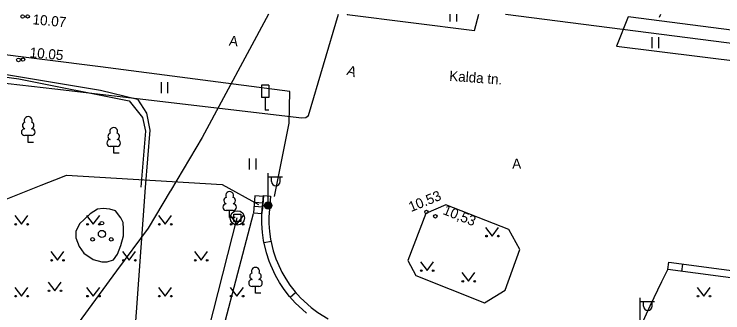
# Model space of a CAD drawing. Extents: x 713497 to 713863, y 6590062 to 6590327.
# Drawn here: x 713659.5 to 713708.83, y 6590306.61 to 6590327.39 of the extents above; entities that cross this region are included whole.
import ezdxf

# ---------------------------------------------------------------- set-up
doc = ezdxf.new("R2010")
doc.units = 0
for name, color, linetype in [('AED', 7, 'Continuous'), ('DKAEV', 7, 'Continuous'), ('HALJASTUS', 7, 'Continuous'), ('HOONE', 7, 'Continuous'), ('KORGUS', 7, 'Continuous'), ('KPKAABEL', 7, 'Continuous'), ('LIIKLUS', 7, 'Continuous'), ('MPKAABEL', 7, 'Continuous'), ('POST', 7, 'Continuous'), ('PUU', 7, 'Continuous'), ('SITRASS', 7, 'Continuous'), ('TEE', 7, 'Continuous'), ('VTRASS', 7, 'Continuous')]:
    doc.layers.add(name, color=color, linetype=linetype)

msp = doc.modelspace()

# ---------------------------------------------------------------- linework, layer by layer
at = {"layer": 'AED'}
for points in [[(713679.847, 6590306.599), (713679.073, 6590307.305), (713678.668, 6590307.755), (713678.294, 6590308.239), (713677.979, 6590308.711), (713677.695, 6590309.209), (713677.362, 6590309.92), (713677.251, 6590310.204), (713677.059, 6590310.788), (713676.86, 6590311.653), (713676.782, 6590312.21), (713676.74, 6590312.819), (713676.737, 6590313.526), (713676.863, 6590314.765), (713676.791, 6590313.828), (713676.863, 6590314.765), (713677.341, 6590314.719), (713677.238, 6590313.258), (713677.24, 6590312.837), (713677.28, 6590312.261), (713677.352, 6590311.744), (713677.541, 6590310.923), (713677.722, 6590310.373), (713677.822, 6590310.117), (713678.139, 6590309.439), (713678.405, 6590308.974), (713678.7, 6590308.532), (713679.053, 6590308.076), (713679.429, 6590307.657), (713680.165, 6590306.986), (713680.628, 6590306.643), (713681.358, 6590306.198)], [(713705.062, 6590310.126), (713726.713, 6590307.265), (713727.852, 6590308.18), (713734.626, 6590314.242), (713739.654, 6590313.67), (713739.599, 6590313.184), (713734.778, 6590313.732), (713728.099, 6590307.754), (713726.875, 6590306.739), (713704.996, 6590309.63)], [(713676.897, 6590311.494), (713677.384, 6590311.607)], [(713704.996, 6590309.63), (713705.062, 6590310.126)], [(713705.988, 6590309.499), (713706.053, 6590309.995)], [(713678.716, 6590307.703), (713679.088, 6590308.037)]]:
    msp.add_lwpolyline(points, dxfattribs=at)
at = {"layer": 'DKAEV'}
for p, q in [((713674.785, 6590312.967), (713674.785, 6590313.467)), ((713674.785, 6590313.467), (713675.285, 6590313.467)), ((713675.285, 6590313.467), (713675.285, 6590312.967)), ((713675.285, 6590312.967), (713674.785, 6590312.967))]:
    msp.add_line(p, q, dxfattribs=at)
msp.add_circle((713675.035, 6590313.217), 0.5, dxfattribs=at)
at = {"layer": 'HALJASTUS'}
for p, q in [((713689.826, 6590327.391), (713689.826, 6590326.888)), ((713690.281, 6590327.391), (713690.281, 6590326.888)), ((713703.899, 6590325.785), (713703.899, 6590325.024)), ((713704.354, 6590325.785), (713704.354, 6590325.024)), ((713669.727, 6590322.66), (713669.727, 6590321.899)), ((713670.182, 6590322.66), (713670.182, 6590321.899)), ((713675.864, 6590317.355), (713675.864, 6590316.594)), ((713676.319, 6590317.355), (713676.319, 6590316.594)), ((713659.547, 6590313.377), (713660.01, 6590312.77)), ((713660.01, 6590312.77), (713660.456, 6590313.377)), ((713664.547, 6590313.377), (713665.01, 6590312.77)), ((713665.01, 6590312.77), (713665.456, 6590313.377)), ((713669.547, 6590313.377), (713670.01, 6590312.77)), ((713670.01, 6590312.77), (713670.456, 6590313.377)), ((713674.547, 6590313.377), (713675.01, 6590312.77)), ((713675.01, 6590312.77), (713675.456, 6590313.377)), ((713692.317, 6590312.557), (713692.78, 6590311.95)), ((713692.78, 6590311.95), (713693.226, 6590312.557)), ((713662.047, 6590310.877), (713662.51, 6590310.27)), ((713662.51, 6590310.27), (713662.956, 6590310.877)), ((713667.047, 6590310.877), (713667.51, 6590310.27)), ((713667.51, 6590310.27), (713667.956, 6590310.877)), ((713672.047, 6590310.877), (713672.51, 6590310.27)), ((713672.51, 6590310.27), (713672.956, 6590310.877)), ((713687.777, 6590310.157), (713688.24, 6590309.55)), ((713688.24, 6590309.55), (713688.686, 6590310.157)), ((713690.667, 6590309.417), (713691.13, 6590308.81)), ((713691.13, 6590308.81), (713691.576, 6590309.417)), ((713661.867, 6590308.747), (713662.33, 6590308.14)), ((713662.33, 6590308.14), (713662.776, 6590308.747)), ((713659.547, 6590308.377), (713660.01, 6590307.77)), ((713660.01, 6590307.77), (713660.456, 6590308.377)), ((713664.547, 6590308.377), (713665.01, 6590307.77)), ((713665.01, 6590307.77), (713665.456, 6590308.377)), ((713669.547, 6590308.377), (713670.01, 6590307.77)), ((713670.01, 6590307.77), (713670.456, 6590308.377)), ((713674.547, 6590308.377), (713675.01, 6590307.77)), ((713675.01, 6590307.77), (713675.456, 6590308.377)), ((713707.047, 6590308.377), (713707.51, 6590307.77)), ((713707.51, 6590307.77), (713707.956, 6590308.377))]:
    msp.add_line(p, q, dxfattribs=at)
msp.add_lwpolyline([(713664.34, 6590310.76), (713665.01, 6590310.33), (713665.61, 6590310.15), (713665.98, 6590310.15), (713666.42, 6590310.3), (713666.7, 6590310.69), (713666.93, 6590311.29), (713667.12, 6590311.97), (713667.12, 6590312.45), (713667.09, 6590312.89), (713666.93, 6590313.23), (713666.55, 6590313.72), (713666.16, 6590313.82), (713665.69, 6590313.87), (713665.31, 6590313.82), (713664.79, 6590313.51), (713664.39, 6590313.14), (713664.06, 6590312.81), (713663.79, 6590312.28), (713663.79, 6590311.83), (713664.02, 6590311.23), (713664.34, 6590310.76)], dxfattribs=at)
for centre, radius in [((713659.609, 6590312.77), 0.055), ((713660.438, 6590312.77), 0.055), ((713664.609, 6590312.77), 0.055), ((713665.438, 6590312.77), 0.055), ((713665.61, 6590312.85), 0.125), ((713669.609, 6590312.77), 0.055), ((713670.438, 6590312.77), 0.055), ((713674.609, 6590312.77), 0.055), ((713675.438, 6590312.77), 0.055), ((713665.61, 6590312.1), 0.25), ((713664.96, 6590311.725), 0.125), ((713666.26, 6590311.725), 0.125), ((713692.379, 6590311.95), 0.055), ((713693.208, 6590311.95), 0.055), ((713662.109, 6590310.27), 0.055), ((713662.938, 6590310.27), 0.055), ((713667.109, 6590310.27), 0.055), ((713667.938, 6590310.27), 0.055), ((713672.109, 6590310.27), 0.055), ((713672.938, 6590310.27), 0.055), ((713687.839, 6590309.55), 0.055), ((713688.668, 6590309.55), 0.055), ((713690.729, 6590308.81), 0.055), ((713691.558, 6590308.81), 0.055), ((713661.929, 6590308.14), 0.055), ((713662.758, 6590308.14), 0.055), ((713659.609, 6590307.77), 0.055), ((713660.438, 6590307.77), 0.055), ((713664.609, 6590307.77), 0.055), ((713665.438, 6590307.77), 0.055), ((713669.609, 6590307.77), 0.055), ((713670.438, 6590307.77), 0.055), ((713674.609, 6590307.77), 0.055), ((713675.438, 6590307.77), 0.055), ((713707.109, 6590307.77), 0.055), ((713707.938, 6590307.77), 0.055)]:
    msp.add_circle(centre, radius, dxfattribs=at)
at = {"layer": 'HOONE'}
msp.add_lwpolyline([(713668.759, 6590288.606), (713675.035, 6590313.217)], dxfattribs=at)
at = {"layer": 'KORGUS'}
for centre, radius in [((713660.09, 6590327.23), 0.125), ((713660.44, 6590327.233), 0.117), ((713659.8, 6590324.21), 0.125), ((713660.115, 6590324.234), 0.117), ((713688.196, 6590313.637), 0.117), ((713688.82, 6590313.33), 0.125)]:
    msp.add_circle(centre, radius, dxfattribs=at)
at = {"layer": 'KPKAABEL'}
for points in [[(713623.883, 6590327.391), (713626.869, 6590326.798), (713637.838, 6590325.546), (713650.945, 6590323.507), (713662.339, 6590322.189), (713679.526, 6590320.171), (713679.807, 6590320.196), (713679.981, 6590320.332), (713682.085, 6590327.391)], [(713627.25, 6590327.391), (713640.869, 6590325.468), (713659.816, 6590322.901), (713667.516, 6590321.371), (713668.425, 6590320.198), (713668.645, 6590319.247), (713668.325, 6590315.363)], [(713629.456, 6590327.391), (713641.981, 6590325.582), (713651.254, 6590324.459), (713665.51, 6590322.099), (713668.075, 6590321.478), (713668.718, 6590320.512), (713668.939, 6590319.317), (713668.609, 6590315.326), (713667.69, 6590302.48)]]:
    msp.add_lwpolyline(points, dxfattribs=at)
at = {"layer": 'LIIKLUS'}
for points in [[(713676.725, 6590322.453), (713676.725, 6590321.603)], [(713677.225, 6590322.453), (713676.725, 6590322.453)], [(713677.225, 6590322.453), (713677.225, 6590321.603)], [(713677.225, 6590321.603), (713676.725, 6590321.603)], [(713676.975, 6590321.603), (713676.975, 6590320.703)], [(713677.225, 6590320.703), (713676.975, 6590320.703)]]:
    msp.add_lwpolyline(points, dxfattribs=at)
at = {"layer": 'MPKAABEL'}
for points in [[(713575.788, 6590327.391), (713592.914, 6590323.282), (713617.232, 6590316.655), (713631.537, 6590314.042), (713645.21, 6590313.241), (713656.126, 6590313.396), (713661.378, 6590315.485), (713662.857, 6590316.074), (713663.141, 6590316.187), (713673.971, 6590315.534), (713676.512, 6590314.151)], [(713693.696, 6590327.391), (713728.086, 6590322.986), (713730.055, 6590322.832), (713732.149, 6590322.669), (713755.92, 6590319.563), (713781.77, 6590316.39), (713783.02, 6590315.71), (713788.916, 6590315.305)], [(713676.139, 6590313.504), (713669.772, 6590289.28), (713669.97, 6590288.316), (713674.295, 6590286.234)]]:
    msp.add_lwpolyline(points, dxfattribs=at)
at = {"layer": 'POST'}
for p, q in [((713677.182, 6590314.332), (713677.182, 6590316.332)), ((713677.182, 6590316.082), (713678.182, 6590316.082)), ((713677.409, 6590315.761), (713677.409, 6590316.082)), ((713678.022, 6590315.761), (713678.022, 6590316.082)), ((713676.264, 6590314.76), (713676.172, 6590313.569)), ((713676.229, 6590314.3), (713676.824, 6590314.254)), ((713676.859, 6590314.714), (713676.264, 6590314.76)), ((713676.768, 6590313.523), (713676.859, 6590314.714)), ((713676.208, 6590314.029), (713676.803, 6590313.983)), ((713676.172, 6590313.569), (713676.768, 6590313.523)), ((713703.081, 6590305.651), (713703.081, 6590307.651)), ((713703.081, 6590307.401), (713704.081, 6590307.401)), ((713703.308, 6590307.08), (713703.308, 6590307.401)), ((713703.92, 6590307.08), (713703.92, 6590307.401))]:
    msp.add_line(p, q, dxfattribs=at)
for radius in [0.25, 0.225, 0.2, 0.175, 0.15, 0.125, 0.1, 0.075, 0.05, 0.025]:
    msp.add_circle((713677.182, 6590314.082), radius, dxfattribs=at)
for centre in [(713677.715, 6590315.761), (713703.614, 6590307.08)]:
    msp.add_arc(centre, 0.306, 180, 0, dxfattribs=at)
at = {"layer": 'PUU'}
for p, q in [((713660.718, 6590318.948), (713660.238, 6590318.948)), ((713660.478, 6590318.473), (713660.478, 6590318.948)), ((713660.858, 6590318.473), (713660.478, 6590318.473)), ((713666.67, 6590318.188), (713666.19, 6590318.188)), ((713666.43, 6590317.713), (713666.43, 6590318.188)), ((713666.81, 6590317.713), (713666.43, 6590317.713)), ((713674.74, 6590313.725), (713674.26, 6590313.725)), ((713674.5, 6590313.25), (713674.5, 6590313.725)), ((713674.88, 6590313.25), (713674.5, 6590313.25)), ((713676.54, 6590308.455), (713676.06, 6590308.455)), ((713676.3, 6590307.98), (713676.3, 6590308.455)), ((713676.68, 6590307.98), (713676.3, 6590307.98))]:
    msp.add_line(p, q, dxfattribs=at)
for centre, radius, start, end in [((713660.478, 6590319.993), 0.277, 332.5799, 207.4201), ((713660.308, 6590319.646), 0.233, 109.0217, 253.1415), ((713660.648, 6590319.646), 0.233, 286.8508, 70.9859), ((713660.241, 6590319.186), 0.238, 90.0016, 269.3953), ((713660.716, 6590319.186), 0.238, 270.6047, 89.9984), ((713666.43, 6590319.233), 0.277, 332.5799, 207.4201), ((713666.26, 6590318.886), 0.233, 109.0217, 253.1415), ((713666.6, 6590318.886), 0.233, 286.8508, 70.9859), ((713666.193, 6590318.425), 0.238, 90.0016, 269.3953), ((713666.667, 6590318.425), 0.238, 270.6047, 89.9984), ((713674.5, 6590314.77), 0.277, 332.5799, 207.4201), ((713674.33, 6590314.423), 0.233, 109.0217, 253.1415), ((713674.67, 6590314.423), 0.233, 286.8508, 70.9859), ((713674.263, 6590313.962), 0.238, 90.0016, 269.3953), ((713674.737, 6590313.962), 0.238, 270.6047, 89.9984), ((713676.13, 6590309.153), 0.233, 109.0217, 253.1415), ((713676.3, 6590309.5), 0.277, 332.5799, 207.4201), ((713676.47, 6590309.153), 0.233, 286.8508, 70.9859), ((713676.063, 6590308.692), 0.238, 90.0016, 269.3953), ((713676.537, 6590308.692), 0.238, 270.6047, 89.9984)]:
    msp.add_arc(centre, radius, start, end, dxfattribs=at)
at = {"layer": 'SITRASS'}
msp.add_lwpolyline([(713677.213, 6590327.391), (713672.58, 6590318.81), (713670.376, 6590315.097), (713670.366, 6590315.08), (713668.84, 6590312.51), (713666.62, 6590309.54), (713652.24, 6590289.93), (713650.28, 6590287.06), (713649.69, 6590286.04)], dxfattribs=at)
at = {"layer": 'TEE'}
for points in [[(713678.644, 6590319.809), (713678.692, 6590322.009), (713665.517, 6590323.727), (713645.548, 6590326.24), (713636.995, 6590327.391)], [(713682.686, 6590327.391), (713682.682, 6590327.366), (713691.549, 6590326.264), (713691.853, 6590327.391)], [(713702.252, 6590327.213), (713701.432, 6590325.163), (713710.214, 6590324.069), (713711.063, 6590326.076), (713702.252, 6590327.213)], [(713677.614, 6590314.7), (713678.644, 6590319.809)], [(713689.546, 6590314.124), (713688.169, 6590313.521)], [(713693.935, 6590312.403), (713689.546, 6590314.124)], [(713688.169, 6590313.521), (713686.906, 6590310.252)], [(713694.71, 6590311.026), (713693.935, 6590312.403)], [(713693.677, 6590308.187), (713694.71, 6590311.026)], [(713686.906, 6590310.252), (713687.451, 6590309.22)], [(713703.04, 6590305.482), (713703.764, 6590307.109), (713704.592, 6590308.787), (713704.997, 6590309.632)], [(713687.451, 6590309.22), (713692.243, 6590307.298)], [(713692.243, 6590307.298), (713693.677, 6590308.187)]]:
    msp.add_lwpolyline(points, dxfattribs=at)
at = {"layer": 'VTRASS'}
msp.add_lwpolyline([(713704.425, 6590327.176), (713704.507, 6590327.391)], dxfattribs=at)

# ---------------------------------------------------------------- texts
at = {"layer": 'KORGUS'}
for s, rotation, p in [('10.07', 354.9392, (713660.76, 6590326.69)), ('10.05', 354.9392, (713660.56, 6590324.39)), ('10.53', 22.1081, (713687.13, 6590313.62)), ('10,53', 338.2574, (713689.293, 6590313.496))]:
    msp.add_text(s, height=0.7, rotation=rotation, dxfattribs=at).set_placement(p)
at = {"layer": 'TEE'}
for s, rotation, p in [('A', 353.0218, (713674.429, 6590325.215)), ('A', 342.2708, (713682.605, 6590323.193)), ('Kalda tn.', 355.8326, (713689.77, 6590322.76)), ('A', 0.527, (713694.172, 6590316.641))]:
    msp.add_text(s, height=0.7, rotation=rotation, dxfattribs=at).set_placement(p)

doc.saveas('drawing.dxf')
